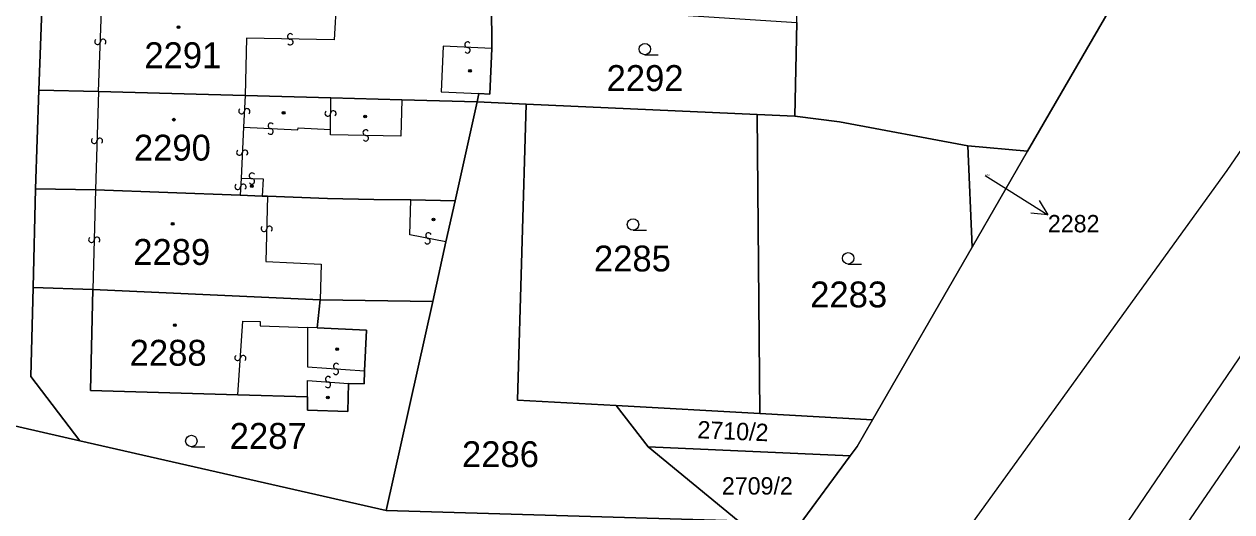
# Model space of a CAD drawing. Extents: x -596024 to -594475, y -1163820 to -1161957.
# Drawn here: x -595797.7 to -595718.4, y -1163063.8 to -1163031.8 of the extents above; entities that cross this region are included whole.
import ezdxf

# ---------------------------------------------------------------- set-up
doc = ezdxf.new("R2010")
doc.units = 0
for name, color, linetype in [('Level 1', 7, 'Continuous'), ('Level 13', 7, 'Continuous'), ('Level 3', 7, 'Continuous'), ('Level 4', 7, 'Continuous'), ('Level 5', 7, 'Continuous'), ('Level 57', 7, 'Continuous'), ('Level 60', 7, 'Continuous')]:
    doc.layers.add(name, color=color, linetype=linetype)

msp = doc.modelspace()

# ---------------------------------------------------------------- linework, layer by layer
at = {"layer": 'Level 1'}
for points in [[(-595796.53, -1163029.64), (-595796.77, -1163036.11)], [(-595725.76, -1163029.61), (-595731.83, -1163040.12)], [(-595767.05, -1163030.39), (-595767.03, -1163033.38)], [(-595747.12, -1163037.82), (-595746.98, -1163031.68)], [(-595767.03, -1163033.38), (-595767.16, -1163036.37), (-595767.87, -1163036.34)], [(-595796.77, -1163036.11), (-595796.99, -1163042.59)], [(-595792.86, -1163036.21), (-595796.77, -1163036.11)], [(-595792.86, -1163036.21), (-595783.23, -1163036.46)], [(-595783.23, -1163036.46), (-595777.6, -1163036.61)], [(-595777.6, -1163036.61), (-595772.94, -1163036.74)], [(-595772.94, -1163036.74), (-595767.99, -1163036.88)], [(-595769.44, -1163043.38), (-595767.99, -1163036.88)], [(-595767.99, -1163036.88), (-595767.87, -1163036.34)], [(-595767.99, -1163036.88), (-595764.76, -1163037.03)], [(-595758.86, -1163056.82), (-595765.33, -1163056.47), (-595764.76, -1163037.03)], [(-595764.76, -1163037.03), (-595749.6, -1163037.71)], [(-595749.41, -1163057.34), (-595749.6, -1163037.71)], [(-595749.6, -1163037.71), (-595747.12, -1163037.82)], [(-595747.12, -1163037.82), (-595744.19, -1163038.19), (-595735.76, -1163039.76)], [(-595735.47, -1163046.42), (-595735.76, -1163039.76)], [(-595731.83, -1163040.12), (-595735.76, -1163039.76)], [(-595731.83, -1163040.12), (-595735.47, -1163046.42)], [(-595796.99, -1163042.59), (-595797.16, -1163049.07)], [(-595793.05, -1163042.67), (-595796.99, -1163042.59)], [(-595793.05, -1163042.67), (-595783.56, -1163043.02)], [(-595783.56, -1163043.02), (-595782.11, -1163043.07)], [(-595782.11, -1163043.07), (-595781.77, -1163043.08)], [(-595772.34, -1163043.32), (-595774.77, -1163043.29), (-595777.82, -1163043.23), (-595781.77, -1163043.08)], [(-595772.34, -1163043.32), (-595769.44, -1163043.38)], [(-595770.04, -1163046.08), (-595769.44, -1163043.38)], [(-595770.91, -1163049.99), (-595770.04, -1163046.08)], [(-595735.47, -1163046.42), (-595742.01, -1163057.76)], [(-595797.16, -1163049.07), (-595797.3, -1163054.91), (-595794.09, -1163059.15)], [(-595793.23, -1163049.21), (-595797.16, -1163049.07)], [(-595793.23, -1163049.21), (-595793.38, -1163055.84), (-595783.7, -1163056.12)], [(-595793.23, -1163049.21), (-595778.29, -1163049.88)], [(-595778.29, -1163049.88), (-595778.5, -1163051.72)], [(-595778.29, -1163049.88), (-595770.91, -1163049.99)], [(-595773.96, -1163063.72), (-595770.91, -1163049.99)], [(-595778.5, -1163051.72), (-595775.25, -1163051.87), (-595775.38, -1163054.55)], [(-595794.09, -1163059.15), (-595812.73, -1163054.87)], [(-595776.43, -1163055.37), (-595775.42, -1163055.4), (-595775.38, -1163054.55)], [(-595779.14, -1163056.25), (-595779.14, -1163057.13), (-595776.49, -1163057.22), (-595776.43, -1163055.37)], [(-595783.7, -1163056.12), (-595779.14, -1163056.25)], [(-595758.86, -1163056.82), (-595756.75, -1163059.54)], [(-595758.86, -1163056.82), (-595749.41, -1163057.34)], [(-595749.41, -1163057.34), (-595742.01, -1163057.76)], [(-595743.48, -1163060.13), (-595743.03, -1163059.52), (-595742.01, -1163057.76)], [(-595794.09, -1163059.15), (-595773.96, -1163063.72)], [(-595756.75, -1163059.54), (-595750.84, -1163064.39)], [(-595756.75, -1163059.54), (-595743.48, -1163060.13)], [(-595746.83, -1163064.67), (-595743.48, -1163060.13)], [(-595773.96, -1163063.72), (-595750.84, -1163064.39)]]:
    msp.add_lwpolyline(points, dxfattribs=at)
at = {"layer": 'Level 13'}
for centre, start, end in [((-595792.924, -1163032.932), 125.27108, 357.36908), ((-595792.556, -1163032.948), 305.05663, 177.64663), ((-595780.256, -1163032.586), 36.06232, 268.65232), ((-595780.265, -1163032.954), 216.27678, 88.37477), ((-595768.611, -1163033.126), 34.45765, 267.04765), ((-595768.63, -1163033.494), 214.67211, 86.7701), ((-595783.464, -1163037.49), 124.14549, 356.73549), ((-595783.096, -1163037.511), 304.35995, 176.45794), ((-595777.804, -1163037.646), 126.54641, 358.64441), ((-595777.436, -1163037.653), 306.33195, 178.92195), ((-595781.54, -1163038.456), 34.65403, 266.75203), ((-595793.144, -1163039.434), 125.47359, 358.06359), ((-595792.776, -1163039.447), 305.68805, 177.78605), ((-595781.56, -1163038.824), 214.43957, 87.02957), ((-595775.305, -1163038.906), 35.92098, 268.51098), ((-595775.316, -1163039.274), 216.13544, 88.23343), ((-595783.604, -1163040.21), 124.41567, 357.00567), ((-595783.236, -1163040.231), 304.63012, 176.72812), ((-595782.772, -1163041.736), 35.3978, 267.4958), ((-595783.714, -1163042.449), 124.11888, 356.70888), ((-595783.346, -1163042.471), 304.33333, 176.43133), ((-595782.787, -1163042.104), 215.18334, 87.77334), ((-595781.994, -1163045.215), 125.95364, 358.54364), ((-595781.626, -1163045.226), 306.16809, 178.26609), ((-595771.184, -1163045.669), 26.12875, 258.71875), ((-595793.324, -1163045.934), 125.58173, 358.17173), ((-595792.956, -1163045.947), 305.79618, 177.89418), ((-595771.257, -1163046.031), 206.3432, 78.4412), ((-595783.724, -1163053.686), 123.59009, 355.68809), ((-595783.356, -1163053.713), 303.37563, 175.96563), ((-595777.245, -1163054.236), 33.26546, 265.36346), ((-595777.274, -1163054.604), 213.051, 85.641), ((-595777.766, -1163055.096), 33.57269, 265.67069), ((-595777.793, -1163055.464), 213.35824, 85.94824)]:
    msp.add_arc(centre, 0.184, start, end, dxfattribs=at)
at = {"layer": 'Level 3'}
for points in [[(-595725.06, -1163069.97), (-595689.64, -1163018.35), (-595669.16, -1162982.86)], [(-595728.81, -1163069.72), (-595688.36, -1163010.24), (-595672.85, -1162983.53)], [(-595738.74, -1163069.07), (-595718.73, -1163041.4), (-595695.75, -1163007.92), (-595682.97, -1162985.08)], [(-595792.86, -1163036.21), (-595792.62, -1163029.67)], [(-595777.22, -1163030.12), (-595777.38, -1163032.82), (-595783.13, -1163032.71), (-595783.23, -1163036.46)], [(-595767.03, -1163033.38), (-595770.21, -1163033.23), (-595770.35, -1163036.23), (-595767.87, -1163036.34)], [(-595792.86, -1163036.21), (-595793.05, -1163042.67)], [(-595783.23, -1163036.46), (-595783.34, -1163038.55)], [(-595777.63, -1163038.69), (-595777.6, -1163036.61)], [(-595772.94, -1163036.74), (-595773, -1163039.14), (-595777.63, -1163039.04), (-595777.63, -1163038.69)], [(-595783.34, -1163038.55), (-595783.5, -1163041.89)], [(-595783.34, -1163038.55), (-595779.76, -1163038.72), (-595779.75, -1163038.59), (-595777.63, -1163038.69)], [(-595783.5, -1163041.89), (-595783.56, -1163043.02)], [(-595783.5, -1163041.89), (-595782.05, -1163041.94), (-595782.11, -1163043.07)], [(-595793.05, -1163042.67), (-595793.23, -1163049.21)], [(-595781.77, -1163043.08), (-595781.86, -1163047.36), (-595778.24, -1163047.55), (-595778.29, -1163049.88)], [(-595770.04, -1163046.08), (-595772.4, -1163045.62), (-595772.34, -1163043.32)], [(-595783.7, -1163056.12), (-595783.38, -1163051.28), (-595782.24, -1163051.31), (-595782.25, -1163051.58), (-595779.13, -1163051.7)], [(-595779.13, -1163051.7), (-595779.14, -1163054.28), (-595775.38, -1163054.55)], [(-595778.5, -1163051.72), (-595779.13, -1163051.7)], [(-595779.14, -1163056.25), (-595779.14, -1163055.19), (-595776.43, -1163055.37)]]:
    msp.add_lwpolyline(points, dxfattribs=at)
at = {"layer": 'Level 5'}
for p, q in [((-595756.97, -1163033.79), (-595756.095, -1163033.79)), ((-595757.75, -1163045.31), (-595756.875, -1163045.31)), ((-595743.62, -1163047.53), (-595742.745, -1163047.53)), ((-595786.76, -1163059.53), (-595785.885, -1163059.53))]:
    msp.add_line(p, q, dxfattribs=at)
for centre, radius in [((-595787.6, -1163031.97), 0.09), ((-595787.6, -1163031.97), 0.0521), ((-595756.97, -1163033.415), 0.375), ((-595768.46, -1163034.85), 0.09), ((-595768.46, -1163034.85), 0.0521), ((-595780.7, -1163037.61), 0.09), ((-595780.7, -1163037.61), 0.0521), ((-595775.35, -1163037.84), 0.09), ((-595787.91, -1163038.05), 0.09), ((-595787.91, -1163038.05), 0.0521), ((-595775.35, -1163037.84), 0.0521), ((-595782.79, -1163042.42), 0.09), ((-595782.79, -1163042.42), 0.0521), ((-595787.99, -1163044.89), 0.09), ((-595787.99, -1163044.89), 0.0521), ((-595770.86, -1163044.6), 0.09), ((-595770.86, -1163044.6), 0.0521), ((-595757.75, -1163044.935), 0.375), ((-595743.62, -1163047.155), 0.375), ((-595787.85, -1163051.54), 0.09), ((-595787.85, -1163051.54), 0.0521), ((-595777.18, -1163053.12), 0.09), ((-595777.18, -1163053.12), 0.0521), ((-595777.8, -1163056.29), 0.09), ((-595777.8, -1163056.29), 0.0521), ((-595786.76, -1163059.155), 0.375)]:
    msp.add_circle(centre, radius, dxfattribs=at)
at = {"layer": 'Level 57'}
for p, q in [((-595734.62, -1163041.72), (-595733.04, -1163042.713)), ((-595733.04, -1163042.713), (-595730.5, -1163044.31))]:
    msp.add_line(p, q, dxfattribs=at)
msp.add_lwpolyline([(-595731.081, -1163043.354), (-595730.5, -1163044.31), (-595731.613, -1163044.201)], dxfattribs=at)
at = {"layer": 'Level 60'}
for points in [[(-595812.73, -1163054.87), (-595809.22, -1163052.29), (-595808.88, -1163036.04), (-595808.61, -1163026.54), (-595808.35, -1163019.93), (-595808.24, -1163010.39), (-595807.83, -1162993.35), (-595811.15, -1162990.23), (-595792.13, -1162988.41), (-595795.85, -1162992.35), (-595796.08, -1163007.03), (-595796.3, -1163016.57), (-595796.51, -1163023.04), (-595796.53, -1163029.64), (-595796.77, -1163036.11), (-595796.99, -1163042.59), (-595797.16, -1163049.07), (-595797.3, -1163054.91), (-595794.09, -1163059.15)], [(-595746.69, -1163018.85), (-595746.58, -1163018.16), (-595725.44, -1163018.91), (-595725.76, -1163029.61), (-595731.83, -1163040.12), (-595735.76, -1163039.76), (-595744.19, -1163038.19), (-595747.12, -1163037.82), (-595746.98, -1163031.68), (-595746.83, -1163025.17)], [(-595796.77, -1163036.11), (-595796.53, -1163029.64), (-595792.62, -1163029.67), (-595782.97, -1163029.95), (-595777.22, -1163030.12), (-595767.05, -1163030.39), (-595767.03, -1163033.38), (-595767.16, -1163036.37), (-595767.87, -1163036.34), (-595767.99, -1163036.88), (-595772.94, -1163036.74), (-595777.6, -1163036.61), (-595783.23, -1163036.46), (-595792.86, -1163036.21)], [(-595746.98, -1163031.68), (-595747.12, -1163037.82), (-595749.6, -1163037.71), (-595764.76, -1163037.03), (-595767.99, -1163036.88), (-595767.87, -1163036.34), (-595767.16, -1163036.37), (-595767.03, -1163033.38), (-595767.05, -1163030.39)], [(-595796.99, -1163042.59), (-595796.77, -1163036.11), (-595792.86, -1163036.21), (-595783.23, -1163036.46), (-595777.6, -1163036.61), (-595772.94, -1163036.74), (-595767.99, -1163036.88), (-595769.44, -1163043.38), (-595772.34, -1163043.32), (-595774.77, -1163043.29), (-595777.82, -1163043.23), (-595781.77, -1163043.08), (-595782.11, -1163043.07), (-595783.56, -1163043.02), (-595793.05, -1163042.67)], [(-595756.75, -1163059.54), (-595750.84, -1163064.39), (-595773.96, -1163063.72), (-595770.91, -1163049.99), (-595770.04, -1163046.08), (-595769.44, -1163043.38), (-595767.99, -1163036.88), (-595764.76, -1163037.03), (-595765.33, -1163056.47), (-595758.86, -1163056.82)], [(-595758.86, -1163056.82), (-595765.33, -1163056.47), (-595764.76, -1163037.03), (-595749.6, -1163037.71), (-595749.41, -1163057.34)], [(-595747.12, -1163037.82), (-595744.19, -1163038.19), (-595735.76, -1163039.76), (-595735.47, -1163046.42), (-595742.01, -1163057.76), (-595749.41, -1163057.34), (-595749.6, -1163037.71)], [(-595735.47, -1163046.42), (-595735.76, -1163039.76), (-595731.83, -1163040.12)], [(-595796.99, -1163042.59), (-595793.05, -1163042.67), (-595783.56, -1163043.02), (-595782.11, -1163043.07), (-595781.77, -1163043.08), (-595777.82, -1163043.23), (-595774.77, -1163043.29), (-595772.34, -1163043.32), (-595769.44, -1163043.38), (-595770.04, -1163046.08), (-595770.91, -1163049.99), (-595778.29, -1163049.88), (-595793.23, -1163049.21), (-595797.16, -1163049.07)], [(-595797.3, -1163054.91), (-595797.16, -1163049.07), (-595793.23, -1163049.21), (-595793.38, -1163055.84), (-595783.7, -1163056.12), (-595779.14, -1163056.25), (-595779.14, -1163057.13), (-595776.49, -1163057.22), (-595776.43, -1163055.37), (-595775.42, -1163055.4), (-595775.38, -1163054.55), (-595775.25, -1163051.87), (-595778.5, -1163051.72), (-595778.29, -1163049.88), (-595770.91, -1163049.99), (-595773.96, -1163063.72), (-595794.09, -1163059.15)], [(-595793.23, -1163049.21), (-595778.29, -1163049.88), (-595778.5, -1163051.72), (-595775.25, -1163051.87), (-595775.38, -1163054.55), (-595775.42, -1163055.4), (-595776.43, -1163055.37), (-595776.49, -1163057.22), (-595779.14, -1163057.13), (-595779.14, -1163056.25), (-595783.7, -1163056.12), (-595793.38, -1163055.84)], [(-595756.75, -1163059.54), (-595758.86, -1163056.82), (-595749.41, -1163057.34), (-595742.01, -1163057.76), (-595743.03, -1163059.52), (-595743.48, -1163060.13)], [(-595750.84, -1163064.39), (-595756.75, -1163059.54), (-595743.48, -1163060.13), (-595746.83, -1163064.67)]]:
    msp.add_lwpolyline(points, close=True, dxfattribs=at)
for points in [[(-595746.83, -1163064.67), (-595743.48, -1163060.13), (-595743.03, -1163059.52), (-595742.01, -1163057.76), (-595735.47, -1163046.42), (-595731.83, -1163040.12), (-595725.76, -1163029.61), (-595719.7, -1163019.11), (-595718.62, -1163017.24), (-595707.44, -1162997.87)], [(-595846.87, -1163047.06), (-595837.67, -1163049.21), (-595828.31, -1163051.33), (-595821.92, -1163052.7), (-595812.73, -1163054.87), (-595794.09, -1163059.15), (-595773.96, -1163063.72), (-595750.84, -1163064.39), (-595757.26, -1163072.39), (-595770.62, -1163069.8), (-595779.65, -1163068.86), (-595798.9, -1163066.88), (-595824.16, -1163062.75), (-595839.42, -1163058.15)]]:
    msp.add_lwpolyline(points, dxfattribs=at)

# ---------------------------------------------------------------- texts
at = {"layer": 'Level 4'}
for s, height, p in [('2291', 1.7, (-595789.85, -1163034.67)), ('2292', 1.7, (-595759.487, -1163036.17)), ('2290', 1.7, (-595790.536, -1163040.74)), ('2282', 0.1, (-595734.62, -1163041.72)), ('2289', 1.7, (-595790.58, -1163047.59)), ('2285', 1.7, (-595760.317, -1163048.02)), ('2283', 1.7, (-595746.113, -1163050.38)), ('2288', 1.7, (-595790.814, -1163054.21)), ('2287', 1.7, (-595784.241, -1163059.67)), ('2286', 1.7, (-595768.986, -1163060.87)), ('2709/2', 1.14, (-595751.914, -1163062.67))]:
    msp.add_text(s, height=height, dxfattribs=at).set_placement(p)
msp.add_text('2710/2', height=1.14, rotation=357.46677, dxfattribs=at).set_placement((-595753.537, -1163058.968))
at = {"layer": 'Level 57'}
msp.add_text('2282', height=1.14, dxfattribs=at).set_placement((-595730.5, -1163045.45))

doc.saveas('drawing.dxf')
